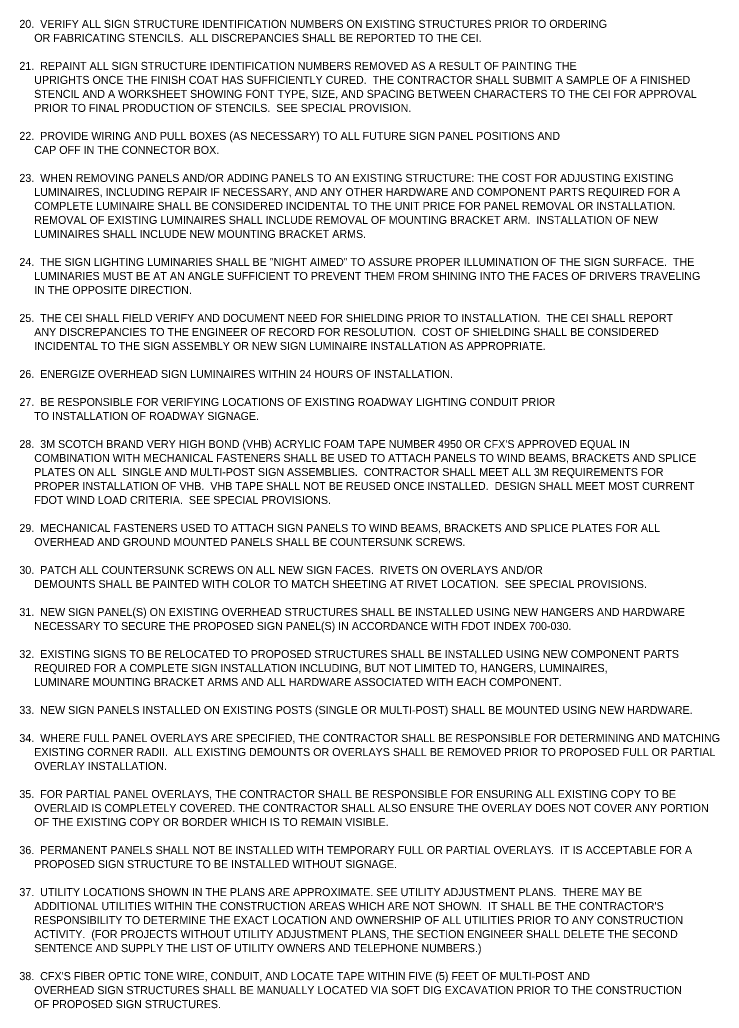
# Model space of a CAD drawing. Extents: x 2479946 to 2483081, y 3677527 to 3681234.
# Drawn here: x 2482492 to 2483081, y 3680359 to 3681193 of the extents above; entities that cross this region are included whole.
import ezdxf

# ---------------------------------------------------------------- set-up
doc = ezdxf.new("R2010")
doc.units = 0
doc.layers.add('40', color=7, linetype='Continuous')

msp = doc.modelspace()

# ---------------------------------------------------------------- texts
at = {"layer": '40'}
for s, p in [('20.  VERIFY ALL SIGN STRUCTURE IDENTIFICATION NUMBERS ON EXISTING STRUCTURES PRIOR TO ORDERING', (2482491.27, 3681185.83)), ('     OR FABRICATING STENCILS.  ALL DISCREPANCIES SHALL BE REPORTED TO THE CEI.', (2482491.27, 3681174.02)), ('21.  REPAINT ALL SIGN STRUCTURE IDENTIFICATION NUMBERS REMOVED AS A RESULT OF PAINTING THE', (2482491.27, 3681150.39)), ('     UPRIGHTS ONCE THE FINISH COAT HAS SUFFICIENTLY CURED.  THE CONTRACTOR SHALL SUBMIT A SAMPLE OF A FINISHED', (2482491.27, 3681138.58)), ('     STENCIL AND A WORKSHEET SHOWING FONT TYPE, SIZE, AND SPACING BETWEEN CHARACTERS TO THE CEI FOR APPROVAL', (2482491.27, 3681126.77)), ('     PRIOR TO FINAL PRODUCTION OF STENCILS.  SEE SPECIAL PROVISION.', (2482491.27, 3681114.95)), ('22.  PROVIDE WIRING AND PULL BOXES (AS NECESSARY) TO ALL FUTURE SIGN PANEL POSITIONS AND ', (2482491.27, 3681091.33)), ('     CAP OFF IN THE CONNECTOR BOX.', (2482491.27, 3681079.52)), ('23.  WHEN REMOVING PANELS AND/OR ADDING PANELS TO AN EXISTING STRUCTURE: THE COST FOR ADJUSTING EXISTING', (2482491.27, 3681055.89)), ('     LUMINAIRES, INCLUDING REPAIR IF NECESSARY, AND ANY OTHER HARDWARE AND COMPONENT PARTS REQUIRED FOR A', (2482491.27, 3681044.08)), ('     COMPLETE LUMINAIRE SHALL BE CONSIDERED INCIDENTAL TO THE UNIT PRICE FOR PANEL REMOVAL OR INSTALLATION.', (2482491.27, 3681032.27)), ('     REMOVAL OF EXISTING LUMINAIRES SHALL INCLUDE REMOVAL OF MOUNTING BRACKET ARM.  INSTALLATION OF NEW', (2482491.27, 3681020.45)), ('     LUMINAIRES SHALL INCLUDE NEW MOUNTING BRACKET ARMS.', (2482491.27, 3681008.64)), ('24.  THE SIGN LIGHTING LUMINARIES SHALL BE "NIGHT AIMED" TO ASSURE PROPER ILLUMINATION OF THE SIGN SURFACE.  THE ', (2482491.27, 3680985.02)), ('     LUMINARIES MUST BE AT AN ANGLE SUFFICIENT TO PREVENT THEM FROM SHINING INTO THE FACES OF DRIVERS TRAVELING ', (2482491.27, 3680973.2)), ('     IN THE OPPOSITE DIRECTION.', (2482491.27, 3680961.39)), ('25.  THE CEI SHALL FIELD VERIFY AND DOCUMENT NEED FOR SHIELDING PRIOR TO INSTALLATION.  THE CEI SHALL REPORT', (2482491.27, 3680937.77)), ('     ANY DISCREPANCIES TO THE ENGINEER OF RECORD FOR RESOLUTION.  COST OF SHIELDING SHALL BE CONSIDERED', (2482491.27, 3680925.95)), ('     INCIDENTAL TO THE SIGN ASSEMBLY OR NEW SIGN LUMINAIRE INSTALLATION AS APPROPRIATE.', (2482491.27, 3680914.14)), ('26.  ENERGIZE OVERHEAD SIGN LUMINAIRES WITHIN 24 HOURS OF INSTALLATION.', (2482491.27, 3680890.52)), ('27.  BE RESPONSIBLE FOR VERIFYING LOCATIONS OF EXISTING ROADWAY LIGHTING CONDUIT PRIOR ', (2482491.27, 3680866.89)), ('     TO INSTALLATION OF ROADWAY SIGNAGE.', (2482491.27, 3680855.08)), ("28.  3M SCOTCH BRAND VERY HIGH BOND (VHB) ACRYLIC FOAM TAPE NUMBER 4950 OR CFX'S APPROVED EQUAL IN ", (2482491.27, 3680831.45)), ('     COMBINATION WITH MECHANICAL FASTENERS SHALL BE USED TO ATTACH PANELS TO WIND BEAMS, BRACKETS AND SPLICE ', (2482491.27, 3680819.64)), ('     PLATES ON ALL  SINGLE AND MULTI-POST SIGN ASSEMBLIES.  CONTRACTOR SHALL MEET ALL 3M REQUIREMENTS FOR', (2482491.27, 3680807.83)), ('     PROPER INSTALLATION OF VHB.  VHB TAPE SHALL NOT BE REUSED ONCE INSTALLED.  DESIGN SHALL MEET MOST CURRENT ', (2482491.27, 3680796.02)), ('     FDOT WIND LOAD CRITERIA.  SEE SPECIAL PROVISIONS.', (2482491.27, 3680784.2)), ('29.  MECHANICAL FASTENERS USED TO ATTACH SIGN PANELS TO WIND BEAMS, BRACKETS AND SPLICE PLATES FOR ALL ', (2482491.27, 3680760.58)), ('     OVERHEAD AND GROUND MOUNTED PANELS SHALL BE COUNTERSUNK SCREWS.', (2482491.27, 3680748.77)), ('30.  PATCH ALL COUNTERSUNK SCREWS ON ALL NEW SIGN FACES.  RIVETS ON OVERLAYS AND/OR ', (2482491.27, 3680725.14)), ('     DEMOUNTS SHALL BE PAINTED WITH COLOR TO MATCH SHEETING AT RIVET LOCATION.  SEE SPECIAL PROVISIONS.', (2482491.27, 3680713.33)), ('31.  NEW SIGN PANEL(S) ON EXISTING OVERHEAD STRUCTURES SHALL BE INSTALLED USING NEW HANGERS AND HARDWARE', (2482491.27, 3680689.7)), ('     NECESSARY TO SECURE THE PROPOSED SIGN PANEL(S) IN ACCORDANCE WITH FDOT INDEX 700-030.  ', (2482491.27, 3680677.89)), ('32.  EXISTING SIGNS TO BE RELOCATED TO PROPOSED STRUCTURES SHALL BE INSTALLED USING NEW COMPONENT PARTS ', (2482491.27, 3680654.27)), ('     REQUIRED FOR A COMPLETE SIGN INSTALLATION INCLUDING, BUT NOT LIMITED TO, HANGERS, LUMINAIRES, ', (2482491.27, 3680642.45)), ('     LUMINARE MOUNTING BRACKET ARMS AND ALL HARDWARE ASSOCIATED WITH EACH COMPONENT.', (2482491.27, 3680630.64)), ('33.  NEW SIGN PANELS INSTALLED ON EXISTING POSTS (SINGLE OR MULTI-POST) SHALL BE MOUNTED USING NEW HARDWARE.', (2482491.27, 3680607.02)), ('34.  WHERE FULL PANEL OVERLAYS ARE SPECIFIED, THE CONTRACTOR SHALL BE RESPONSIBLE FOR DETERMINING AND MATCHING', (2482491.27, 3680583.39)), ('     EXISTING CORNER RADII.  ALL EXISTING DEMOUNTS OR OVERLAYS SHALL BE REMOVED PRIOR TO PROPOSED FULL OR PARTIAL', (2482491.27, 3680571.58)), ('     OVERLAY INSTALLATION.', (2482491.27, 3680559.77)), ('35.  FOR PARTIAL PANEL OVERLAYS, THE CONTRACTOR SHALL BE RESPONSIBLE FOR ENSURING ALL EXISTING COPY TO BE', (2482491.27, 3680536.14)), ('     OVERLAID IS COMPLETELY COVERED. THE CONTRACTOR SHALL ALSO ENSURE THE OVERLAY DOES NOT COVER ANY PORTION', (2482491.27, 3680524.33)), ('     OF THE EXISTING COPY OR BORDER WHICH IS TO REMAIN VISIBLE.', (2482491.27, 3680512.52)), ('36.  PERMANENT PANELS SHALL NOT BE INSTALLED WITH TEMPORARY FULL OR PARTIAL OVERLAYS.  IT IS ACCEPTABLE FOR A', (2482491.27, 3680488.89)), ('     PROPOSED SIGN STRUCTURE TO BE INSTALLED WITHOUT SIGNAGE.', (2482491.27, 3680477.08)), ('37.  UTILITY LOCATIONS SHOWN IN THE PLANS ARE APPROXIMATE. SEE UTILITY ADJUSTMENT PLANS.  THERE MAY BE ', (2482491.27, 3680453.45)), ("     ADDITIONAL UTILITIES WITHIN THE CONSTRUCTION AREAS WHICH ARE NOT SHOWN.  IT SHALL BE THE CONTRACTOR'S ", (2482491.27, 3680441.64)), ('     RESPONSIBILITY TO DETERMINE THE EXACT LOCATION AND OWNERSHIP OF ALL UTILITIES PRIOR TO ANY CONSTRUCTION ', (2482491.27, 3680429.83)), ('     ACTIVITY.  (FOR PROJECTS WITHOUT UTILITY ADJUSTMENT PLANS, THE SECTION ENGINEER SHALL DELETE THE SECOND', (2482491.27, 3680418.02)), ('     SENTENCE AND SUPPLY THE LIST OF UTILITY OWNERS AND TELEPHONE NUMBERS.)', (2482491.27, 3680406.2)), ("38.  CFX'S FIBER OPTIC TONE WIRE, CONDUIT, AND LOCATE TAPE WITHIN FIVE (5) FEET OF MULTI-POST AND ", (2482491.27, 3680382.58)), ('     OVERHEAD SIGN STRUCTURES SHALL BE MANUALLY LOCATED VIA SOFT DIG EXCAVATION PRIOR TO THE CONSTRUCTION ', (2482491.27, 3680370.77)), ('     OF PROPOSED SIGN STRUCTURES.', (2482491.27, 3680358.95))]:
    msp.add_text(s, height=6.75, dxfattribs=at).set_placement(p)

doc.saveas('drawing.dxf')
